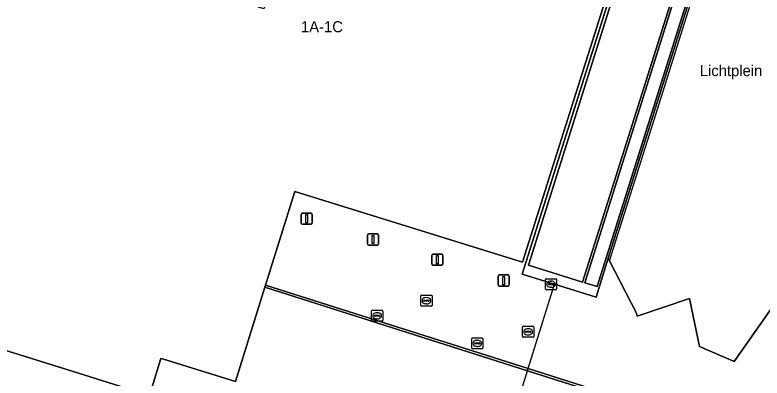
# Model space of a CAD drawing. Extents: x 160675 to 161153, y 383241 to 383714.
# Drawn here: x 160986.7 to 161054.2, y 383375 to 383407.9 of the extents above; entities that cross this region are included whole.
import ezdxf

# ---------------------------------------------------------------- set-up
doc = ezdxf.new("R2010")
doc.units = 0
for name, color, linetype in [('IMGEO_Groenvoorziening', 7, 'Continuous'), ('IMGEO_Kolk', 7, 'Continuous'), ('IMGEO_Lichtmast', 7, 'Continuous'), ('IMGEO_Lijnafwatering', 7, 'Continuous'), ('IMGEO_Muur', 7, 'Continuous'), ('IMGEO_Openbare_ruimte_label', 7, 'Continuous'), ('IMGEO_Pand', 7, 'Continuous'), ('IMGEO_Pand_nummerreeks', 7, 'Continuous'), ('IMGEO_Rijbaan_lokaal_open', 7, 'Continuous'), ('IMGEO_Rioolput', 7, 'Continuous'), ('IMGEO_Voetgangersgebied_open', 7, 'Continuous'), ('IMGEO_Voetpad_gesloten', 7, 'Continuous'), ('IMGEO_Voetpad_open', 7, 'Continuous')]:
    doc.layers.add(name, color=color, linetype=linetype)

msp = doc.modelspace()

# ---------------------------------------------------------------- linework, layer by layer
at = {"layer": 'IMGEO_Groenvoorziening'}
msp.add_lwpolyline([(161039.284, 383383.304), (161050.181, 383418.024), (161049.074, 383418.364), (161038.161, 383383.655)], close=True, dxfattribs=at)
at = {"layer": 'IMGEO_Kolk'}
for p, q in [((161034.699, 383384.021), (161035.551, 383384.021)), ((161034.624, 383383.095), (161034.624, 383383.947)), ((161034.883, 383383.515), (161034.883, 383383.527)), ((161035.321, 383383.478), (161034.923, 383383.478)), ((161034.926, 383383.564), (161035.324, 383383.564)), ((161035.112, 383383.801), (161035.137, 383383.801)), ((161035.367, 383383.527), (161035.367, 383383.515)), ((161035.625, 383383.947), (161035.625, 383383.095)), ((161035.551, 383383.021), (161034.699, 383383.021)), ((161035.135, 383383.241), (161035.11, 383383.241)), ((161018.903, 383380.242), (161018.903, 383381.094)), ((161018.978, 383381.168), (161019.83, 383381.168)), ((161019.162, 383380.662), (161019.162, 383380.674)), ((161019.6, 383380.625), (161019.202, 383380.625)), ((161019.205, 383380.711), (161019.603, 383380.711)), ((161019.391, 383380.948), (161019.416, 383380.948)), ((161019.646, 383380.674), (161019.646, 383380.662)), ((161019.904, 383381.094), (161019.904, 383380.242)), ((161019.83, 383380.168), (161018.978, 383380.168)), ((161019.414, 383380.388), (161019.389, 383380.388)), ((161027.959, 383377.748), (161027.959, 383378.6)), ((161028.034, 383378.674), (161028.886, 383378.674)), ((161028.96, 383378.6), (161028.96, 383377.748)), ((161028.218, 383378.168), (161028.218, 383378.18)), ((161028.656, 383378.131), (161028.258, 383378.131)), ((161028.261, 383378.217), (161028.659, 383378.217)), ((161028.447, 383378.454), (161028.472, 383378.454)), ((161028.702, 383378.18), (161028.702, 383378.168)), ((161028.886, 383377.674), (161028.034, 383377.674)), ((161028.47, 383377.894), (161028.445, 383377.894))]:
    msp.add_line(p, q, dxfattribs=at)
for points in [[(161034.699, 383384.021), (161035.551, 383384.021)], [(161034.624, 383383.095), (161034.624, 383383.947)], [(161035.625, 383383.947), (161035.625, 383383.095)], [(161035.551, 383383.021), (161034.699, 383383.021)], [(161018.903, 383380.242), (161018.903, 383381.094)], [(161018.978, 383381.168), (161019.83, 383381.168)], [(161019.904, 383381.094), (161019.904, 383380.242)], [(161019.83, 383380.168), (161018.978, 383380.168)], [(161027.959, 383377.748), (161027.959, 383378.6)], [(161028.034, 383378.674), (161028.886, 383378.674)], [(161028.96, 383378.6), (161028.96, 383377.748)], [(161028.886, 383377.674), (161028.034, 383377.674)]]:
    msp.add_lwpolyline(points, dxfattribs=at)
for centre, radius, start, end in [((161034.701, 383383.945), 0.0765, 91.55205, 178.44795), ((161034.701, 383383.945), 0.0765, 91.55205, 178.44795), ((161035.549, 383383.945), 0.0765, 1.55205, 88.44795), ((161035.549, 383383.945), 0.0765, 1.55205, 88.44795), ((161034.923, 383383.524), 0.0403, 85.87752, 175.75265), ((161034.92, 383383.514), 0.0366, 178.93798, 274.71019), ((161035.324, 383383.521), 0.043, 264.86636, 352.45326), ((161035.328, 383383.526), 0.0386, 1.73085, 96.63898), ((161034.701, 383383.097), 0.0765, 181.55205, 268.44795), ((161034.701, 383383.097), 0.0765, 181.55205, 268.44795), ((161035.549, 383383.097), 0.0765, 271.55205, 358.44795), ((161035.549, 383383.097), 0.0765, 271.55205, 358.44795), ((161018.98, 383381.092), 0.0765, 91.55205, 178.44795), ((161018.98, 383381.092), 0.0765, 91.55205, 178.44795), ((161019.202, 383380.671), 0.0403, 85.87752, 175.75265), ((161019.199, 383380.661), 0.0366, 178.93798, 274.71019), ((161019.603, 383380.668), 0.043, 264.86636, 352.45326), ((161019.607, 383380.673), 0.0386, 1.73085, 96.63898), ((161019.828, 383381.092), 0.0765, 1.55205, 88.44795), ((161019.828, 383381.092), 0.0765, 1.55205, 88.44795), ((161018.98, 383380.244), 0.0765, 181.55205, 268.44795), ((161018.98, 383380.244), 0.0765, 181.55205, 268.44795), ((161019.828, 383380.244), 0.0765, 271.55205, 358.44795), ((161019.828, 383380.244), 0.0765, 271.55205, 358.44795), ((161028.036, 383378.598), 0.0765, 91.55205, 178.44795), ((161028.036, 383378.598), 0.0765, 91.55205, 178.44795), ((161028.884, 383378.598), 0.0765, 1.55205, 88.44795), ((161028.884, 383378.598), 0.0765, 1.55205, 88.44795), ((161028.258, 383378.177), 0.0403, 85.87752, 175.75265), ((161028.255, 383378.167), 0.0366, 178.93798, 274.71019), ((161028.659, 383378.174), 0.043, 264.86636, 352.45326), ((161028.663, 383378.179), 0.0386, 1.73085, 96.63898), ((161028.036, 383377.75), 0.0765, 181.55205, 268.44795), ((161028.036, 383377.75), 0.0765, 181.55205, 268.44795), ((161028.884, 383377.75), 0.0765, 271.55205, 358.44795), ((161028.884, 383377.75), 0.0765, 271.55205, 358.44795)]:
    msp.add_arc(centre, radius, start, end, dxfattribs=at)
for centre, major_axis, ratio, start_param, end_param in [((161035.111, 383383.521), (-0.387, 0.002), 0.722429, 4.712389, 7.853982), ((161035.136, 383383.521), (-0.39, 0.002), 0.717154, 1.570796, 4.712389), ((161019.39, 383380.668), (-0.387, 0.002), 0.722429, 4.712389, 7.853982), ((161019.415, 383380.668), (-0.39, 0.002), 0.717154, 1.570796, 4.712389), ((161028.446, 383378.174), (-0.387, 0.002), 0.722429, 4.712389, 7.853982), ((161028.471, 383378.174), (-0.39, 0.002), 0.717154, 1.570796, 4.712389)]:
    msp.add_ellipse(centre, major_axis=major_axis, ratio=ratio, start_param=start_param, end_param=end_param, dxfattribs=at)
at = {"layer": 'IMGEO_Lichtmast'}
for p, q in [((161012.549, 383389.042), (161012.549, 383389.842)), ((161012.549, 383389.842), (161012.549, 383389.042)), ((161012.649, 383389.942), (161013.439, 383389.942)), ((161013.439, 383389.942), (161012.649, 383389.942)), ((161013.539, 383389.842), (161013.539, 383389.042)), ((161013.539, 383389.042), (161013.539, 383389.842)), ((161013.439, 383388.942), (161012.649, 383388.942)), ((161012.649, 383388.942), (161013.439, 383388.942)), ((161018.644, 383388.068), (161019.434, 383388.068)), ((161019.434, 383388.068), (161018.644, 383388.068)), ((161018.544, 383387.168), (161018.544, 383387.968)), ((161018.544, 383387.968), (161018.544, 383387.168)), ((161019.534, 383387.968), (161019.534, 383387.168)), ((161019.534, 383387.168), (161019.534, 383387.968)), ((161019.434, 383387.068), (161018.644, 383387.068)), ((161018.644, 383387.068), (161019.434, 383387.068)), ((161024.348, 383385.333), (161024.348, 383386.133)), ((161024.348, 383386.133), (161024.348, 383385.333)), ((161024.448, 383386.233), (161025.238, 383386.233)), ((161025.238, 383386.233), (161024.448, 383386.233)), ((161025.338, 383386.133), (161025.338, 383385.333)), ((161025.338, 383385.333), (161025.338, 383386.133)), ((161025.238, 383385.233), (161024.448, 383385.233)), ((161024.448, 383385.233), (161025.238, 383385.233)), ((161030.341, 383383.457), (161030.341, 383384.257)), ((161030.341, 383384.257), (161030.341, 383383.457)), ((161030.441, 383384.357), (161031.231, 383384.357)), ((161031.231, 383384.357), (161030.441, 383384.357)), ((161031.331, 383384.257), (161031.331, 383383.457)), ((161031.331, 383383.457), (161031.331, 383384.257)), ((161031.231, 383383.357), (161030.441, 383383.357)), ((161030.441, 383383.357), (161031.231, 383383.357))]:
    msp.add_line(p, q, dxfattribs=at)
for points in [[(161012.969, 383389.817), (161013.119, 383389.817), (161013.119, 383389.067), (161012.969, 383389.067), (161012.969, 383389.817)], [(161018.964, 383387.943), (161019.114, 383387.943), (161019.114, 383387.193), (161018.964, 383387.193), (161018.964, 383387.943)], [(161024.768, 383386.108), (161024.918, 383386.108), (161024.918, 383385.358), (161024.768, 383385.358), (161024.768, 383386.108)], [(161030.761, 383384.232), (161030.911, 383384.232), (161030.911, 383383.482), (161030.761, 383383.482), (161030.761, 383384.232)]]:
    msp.add_lwpolyline(points, dxfattribs=at)
for centre, start, end in [((161012.649, 383389.842), 90, 180), ((161012.649, 383389.842), 90, 180), ((161013.439, 383389.842), 0, 90), ((161013.439, 383389.842), 360, 90), ((161012.649, 383389.042), 180, 270), ((161012.649, 383389.042), 180, 270), ((161013.439, 383389.042), 270, 0), ((161013.439, 383389.042), 270, 0), ((161018.644, 383387.968), 90, 180), ((161018.644, 383387.968), 90, 180), ((161019.434, 383387.968), 0, 90), ((161019.434, 383387.968), 360, 90), ((161018.644, 383387.168), 180, 270), ((161018.644, 383387.168), 180, 270), ((161019.434, 383387.168), 270, 0), ((161019.434, 383387.168), 270, 0), ((161024.448, 383386.133), 90, 180), ((161024.448, 383386.133), 90, 180), ((161025.238, 383386.133), 0, 90), ((161025.238, 383386.133), 360, 90), ((161024.448, 383385.333), 180, 270), ((161024.448, 383385.333), 180, 270), ((161025.238, 383385.333), 270, 0), ((161025.238, 383385.333), 270, 0), ((161030.441, 383384.257), 90, 180), ((161030.441, 383384.257), 90, 180), ((161031.231, 383384.257), 0, 90), ((161031.231, 383384.257), 360, 90), ((161030.441, 383383.457), 180, 270), ((161030.441, 383383.457), 180, 270), ((161031.231, 383383.457), 270, 0), ((161031.231, 383383.457), 270, 0)]:
    msp.add_arc(centre, 0.1, start, end, dxfattribs=at)
at = {"layer": 'IMGEO_Lijnafwatering'}
for points in [[(161046.662, 383405.512), (161048.746, 383412.14), (161052.914, 383425.398)], [(161040.41, 383385.625), (161044.578, 383398.883), (161046.662, 383405.512)], [(161030.016, 383366.136), (161032.993, 383375.695), (161033.053, 383375.886), (161035.432, 383383.524)]]:
    msp.add_lwpolyline(points, dxfattribs=at)
at = {"layer": 'IMGEO_Muur'}
for points in [[(161049.551, 383426.438), (161046.083, 383427.531), (161032.515, 383384.431), (161035.432, 383383.524), (161039.196, 383382.354), (161040.28, 383385.878), (161052.723, 383425.456), (161051.429, 383425.846), (161051.214, 383425.911)], [(161048.883, 383418.423), (161037.97, 383383.715), (161033.081, 383385.244), (161043.97, 383419.933), (161045.017, 383423.27), (161046.236, 383427.152), (161051.143, 383425.655), (161049.92, 383421.775)], [(161039.284, 383383.304), (161038.161, 383383.655), (161049.074, 383418.364), (161050.181, 383418.024)]]:
    msp.add_lwpolyline(points, close=True, dxfattribs=at)
at = {"layer": 'IMGEO_Pand'}
msp.add_lwpolyline([(160984.676, 383377.898), (160992.903, 383375.323), (160998.821, 383373.471), (160999.845, 383376.812), (161000, 383376.764), (161006.596, 383374.71), (161009.264, 383383.247), (161009.323, 383383.438), (161011.968, 383391.902), (161032.552, 383385.506), (161045.909, 383427.885), (161047.883, 383434.148), (161032.528, 383430.873), (161029.611, 383430.31), (161022.993, 383428.609), (161021.266, 383423.165), (161016.995, 383409.701), (161010.218, 383411.816), (161009.156, 383408.436), (161000, 383411.313), (160995.072, 383412.862), (160990.957, 383414.155), (160967.849, 383421.416)], dxfattribs=at)
at = {"layer": 'IMGEO_Rijbaan_lokaal_open'}
msp.add_lwpolyline([(160984.25, 383368.29), (160983.844, 383366.986), (160983.014, 383364.509), (160988.884, 383362.56), (160989.043, 383363.059), (160989.388, 383362.949), (160989.553, 383363.376), (160989.861, 383363.276), (160989.662, 383362.626), (160991.539, 383362.053), (160991.734, 383362.661), (160991.943, 383362.588), (160992.073, 383362.982), (160995.127, 383362.001), (160998.821, 383373.471), (160992.903, 383375.323), (160984.676, 383377.898), (160984.628, 383377.743), (160983.694, 383374.772), (160964.526, 383380.856), (160964.061, 383380.631)], dxfattribs=at)
at = {"layer": 'IMGEO_Rioolput'}
for p, q in [((161023.362, 383381.607), (161023.362, 383382.459)), ((161023.437, 383382.533), (161024.289, 383382.533)), ((161023.621, 383382.027), (161023.621, 383382.039)), ((161024.059, 383381.99), (161023.661, 383381.99)), ((161023.664, 383382.076), (161024.062, 383382.076)), ((161023.85, 383382.313), (161023.875, 383382.313)), ((161024.105, 383382.039), (161024.105, 383382.027)), ((161024.363, 383382.459), (161024.363, 383381.607)), ((161024.289, 383381.533), (161023.437, 383381.533)), ((161023.873, 383381.753), (161023.848, 383381.753)), ((161032.551, 383378.794), (161032.551, 383379.646)), ((161032.626, 383379.72), (161033.478, 383379.72)), ((161033.039, 383379.5), (161033.064, 383379.5)), ((161033.552, 383379.646), (161033.552, 383378.794)), ((161033.478, 383378.72), (161032.626, 383378.72)), ((161032.81, 383379.214), (161032.81, 383379.226)), ((161033.248, 383379.177), (161032.85, 383379.177)), ((161032.853, 383379.263), (161033.251, 383379.263)), ((161033.062, 383378.94), (161033.037, 383378.94)), ((161033.294, 383379.226), (161033.294, 383379.214))]:
    msp.add_line(p, q, dxfattribs=at)
for points in [[(161023.362, 383381.607), (161023.362, 383382.459)], [(161023.437, 383382.533), (161024.289, 383382.533)], [(161024.363, 383382.459), (161024.363, 383381.607)], [(161024.289, 383381.533), (161023.437, 383381.533)], [(161032.551, 383378.794), (161032.551, 383379.646)], [(161032.626, 383379.72), (161033.478, 383379.72)], [(161033.552, 383379.646), (161033.552, 383378.794)], [(161033.478, 383378.72), (161032.626, 383378.72)]]:
    msp.add_lwpolyline(points, dxfattribs=at)
for centre, radius, start, end in [((161023.439, 383382.457), 0.0765, 91.55205, 178.44795), ((161023.439, 383382.457), 0.0765, 91.55205, 178.44795), ((161023.661, 383382.036), 0.0403, 85.87752, 175.75265), ((161023.658, 383382.026), 0.0366, 178.93798, 274.71019), ((161024.062, 383382.033), 0.043, 264.86636, 352.45326), ((161024.066, 383382.038), 0.0386, 1.73085, 96.63898), ((161024.287, 383382.457), 0.0765, 1.55205, 88.44795), ((161024.287, 383382.457), 0.0765, 1.55205, 88.44795), ((161023.439, 383381.609), 0.0765, 181.55205, 268.44795), ((161023.439, 383381.609), 0.0765, 181.55205, 268.44795), ((161024.287, 383381.609), 0.0765, 271.55205, 358.44795), ((161024.287, 383381.609), 0.0765, 271.55205, 358.44795), ((161032.628, 383379.644), 0.0765, 91.55205, 178.44795), ((161032.628, 383379.644), 0.0765, 91.55205, 178.44795), ((161033.476, 383379.644), 0.0765, 1.55205, 88.44795), ((161033.476, 383379.644), 0.0765, 1.55205, 88.44795), ((161032.628, 383378.796), 0.0765, 181.55205, 268.44795), ((161032.628, 383378.796), 0.0765, 181.55205, 268.44795), ((161032.85, 383379.223), 0.0403, 85.87752, 175.75265), ((161032.847, 383379.213), 0.0366, 178.93798, 274.71019), ((161033.251, 383379.22), 0.043, 264.86636, 352.45326), ((161033.255, 383379.225), 0.0386, 1.73085, 96.63898), ((161033.476, 383378.796), 0.0765, 271.55205, 358.44795), ((161033.476, 383378.796), 0.0765, 271.55205, 358.44795)]:
    msp.add_arc(centre, radius, start, end, dxfattribs=at)
for centre, major_axis, ratio, start_param, end_param in [((161023.849, 383382.033), (-0.387, 0.002), 0.722429, 4.712389, 7.853982), ((161023.874, 383382.033), (-0.39, 0.002), 0.717154, 1.570796, 4.712389), ((161033.038, 383379.22), (-0.387, 0.002), 0.722429, 4.712389, 7.853982), ((161033.063, 383379.22), (-0.39, 0.002), 0.717154, 1.570796, 4.712389)]:
    msp.add_ellipse(centre, major_axis=major_axis, ratio=ratio, start_param=start_param, end_param=end_param, dxfattribs=at)
at = {"layer": 'IMGEO_Voetgangersgebied_open'}
for points in [[(161045.909, 383427.885), (161032.552, 383385.506), (161011.968, 383391.902), (161009.323, 383383.438), (161033.053, 383375.886), (161055.334, 383368.796)], [(161072.736, 383422.509), (161061.981, 383388.875), (161061.791, 383388.956), (161060.03, 383388.472), (161051.68, 383376.521), (161048.527, 383377.888), (161047.628, 383382.235), (161042.897, 383380.639), (161042.849, 383380.891), (161040.41, 383385.625), (161040.28, 383385.878), (161039.196, 383382.354), (161035.432, 383383.524), (161032.515, 383384.431), (161046.083, 383427.531)]]:
    msp.add_lwpolyline(points, dxfattribs=at)
msp.add_lwpolyline([(161062.237, 383366.382), (161055.712, 383368.464), (161055.286, 383368.6), (161032.993, 383375.695), (161009.264, 383383.247), (161006.596, 383374.71), (161000, 383376.764), (160999.845, 383376.812), (160998.821, 383373.471), (160995.127, 383362.001), (161000, 383360.437), (161012.145, 383356.538), (161012.028, 383356.167), (161012.311, 383356.101), (161009.904, 383348.868), (161015.941, 383346.9), (161017.412, 383351.416), (161020.898, 383350.298), (161019.467, 383345.797), (161050.252, 383335.927), (161052.382, 383335.311)], close=True, dxfattribs=at)
at = {"layer": 'IMGEO_Voetpad_gesloten'}
msp.add_lwpolyline([(161048.883, 383418.423), (161049.92, 383421.775), (161051.143, 383425.655), (161046.236, 383427.152), (161045.017, 383423.27), (161043.97, 383419.933), (161033.081, 383385.244), (161037.97, 383383.715)], close=True, dxfattribs=at)
at = {"layer": 'IMGEO_Voetpad_open'}
msp.add_lwpolyline([(161052.723, 383425.456), (161040.28, 383385.878), (161040.41, 383385.625), (161042.849, 383380.891), (161042.897, 383380.639), (161047.628, 383382.235), (161048.527, 383377.888), (161051.68, 383376.521), (161060.03, 383388.472), (161061.791, 383388.956), (161061.981, 383388.875), (161072.736, 383422.509)], dxfattribs=at)
msp.add_lwpolyline([(161055.773, 383368.656), (161055.334, 383368.796), (161033.053, 383375.886), (161009.323, 383383.438), (161009.264, 383383.247), (161032.993, 383375.695), (161055.286, 383368.6), (161055.712, 383368.464), (161062.237, 383366.382), (161062.298, 383366.573)], close=True, dxfattribs=at)

# ---------------------------------------------------------------- texts
at = {"layer": 'IMGEO_Openbare_ruimte_label'}
msp.add_text('Lichtplein', height=1, dxfattribs=at).set_placement((161048.56, 383402.344))
at = {"layer": 'IMGEO_Pand_nummerreeks'}
msp.add_text('1A-1C', height=1, dxfattribs=at).set_placement((161012.523, 383406.315))

doc.saveas('drawing.dxf')
